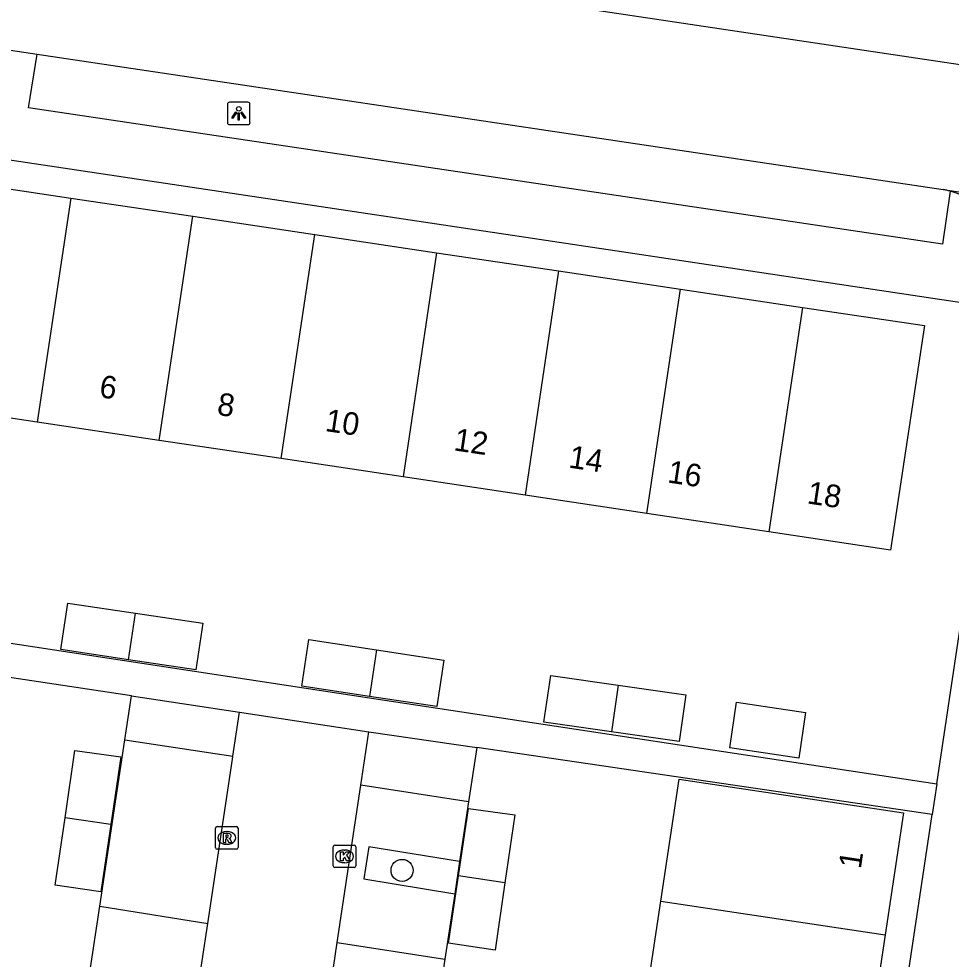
# Model space of a CAD drawing. Extents: x 164150 to 165261, y 382513 to 383432.
# Drawn here: x 164272.17 to 164313.46, y 382840.05 to 382881.72 of the extents above; entities that cross this region are included whole.
import ezdxf

# ---------------------------------------------------------------- set-up
doc = ezdxf.new("R2010")
doc.units = 0
for name, color, linetype in [('IMGEO_Boom', 7, 'Continuous'), ('IMGEO_Groenvoorziening', 7, 'Continuous'), ('IMGEO_Kolk', 7, 'Continuous'), ('IMGEO_Lichtpunt', 7, 'Continuous'), ('IMGEO_Pand', 7, 'Continuous'), ('IMGEO_Pand_nummerreeks', 7, 'Continuous'), ('IMGEO_Parkeervlak_open', 7, 'Continuous'), ('IMGEO_Rijbaan_lokaal_gesloten', 7, 'Continuous'), ('IMGEO_Rijbaan_lokaal_open', 7, 'Continuous'), ('IMGEO_Rioolput', 7, 'Continuous'), ('IMGEO_Voetpad_open', 7, 'Continuous')]:
    doc.layers.add(name, color=color, linetype=linetype)

msp = doc.modelspace()

# ---------------------------------------------------------------- linework, layer by layer
at = {"layer": 'IMGEO_Boom'}
msp.add_circle((164289.145, 382843.98), 0.489, dxfattribs=at)
at = {"layer": 'IMGEO_Groenvoorziening'}
msp.add_lwpolyline([(164291.688, 382844.368), (164291.474, 382842.945)], dxfattribs=at)
at = {"layer": 'IMGEO_Kolk'}
for p, q in [((164286.092, 382844.176), (164286.092, 382845.028)), ((164286.167, 382845.102), (164287.019, 382845.102)), ((164286.58, 382844.882), (164286.605, 382844.882)), ((164287.093, 382845.028), (164287.093, 382844.176)), ((164287.019, 382844.102), (164286.167, 382844.102)), ((164286.603, 382844.322), (164286.578, 382844.322))]:
    msp.add_line(p, q, dxfattribs=at)
for points in [[(164286.092, 382844.176), (164286.092, 382845.028)], [(164286.167, 382845.102), (164287.019, 382845.102)], [(164287.093, 382845.028), (164287.093, 382844.176)], [(164286.413, 382844.802), (164286.536, 382844.802), (164286.536, 382844.651), (164286.666, 382844.802), (164286.83, 382844.802), (164286.684, 382844.651), (164286.837, 382844.402), (164286.685, 382844.402), (164286.6, 382844.566), (164286.536, 382844.499), (164286.536, 382844.402), (164286.413, 382844.402), (164286.413, 382844.802)], [(164287.019, 382844.102), (164286.167, 382844.102)]]:
    msp.add_lwpolyline(points, dxfattribs=at)
for centre, start, end in [((164286.169, 382845.026), 91.552, 178.448), ((164286.169, 382845.026), 91.552, 178.448), ((164287.017, 382845.026), 1.552, 88.448), ((164287.017, 382845.026), 1.552, 88.448), ((164286.169, 382844.178), 181.552, 268.448), ((164286.169, 382844.178), 181.552, 268.448), ((164287.017, 382844.178), 271.552, 358.448), ((164287.017, 382844.178), 271.552, 358.448)]:
    msp.add_arc(centre, 0.0765, start, end, dxfattribs=at)
for centre, major_axis, ratio, start_param, end_param in [((164286.579, 382844.602), (-0.387, 0.002), 0.722429, 4.712389, 7.853982), ((164286.604, 382844.602), (-0.39, 0.002), 0.717154, 1.570796, 4.712389)]:
    msp.add_ellipse(centre, major_axis=major_axis, ratio=ratio, start_param=start_param, end_param=end_param, dxfattribs=at)
at = {"layer": 'IMGEO_Lichtpunt'}
for p, q in [((164281.411, 382877.927), (164281.411, 382877.12)), ((164281.411, 382877.927), (164281.411, 382877.12)), ((164282.313, 382878.022), (164281.505, 382878.022)), ((164282.313, 382878.022), (164281.505, 382878.022)), ((164282.407, 382877.12), (164282.407, 382877.927)), ((164282.407, 382877.12), (164282.407, 382877.927)), ((164281.505, 382877.026), (164282.313, 382877.026)), ((164281.505, 382877.026), (164282.313, 382877.026))]:
    msp.add_line(p, q, dxfattribs=at)
for points in [[(164281.785, 382877.591), (164281.824, 382877.563), (164281.636, 382877.301), (164281.598, 382877.328), (164281.785, 382877.591)], [(164281.887, 382877.543), (164281.934, 382877.543), (164281.934, 382877.221), (164281.887, 382877.221), (164281.887, 382877.543)], [(164281.997, 382877.563), (164282.035, 382877.59), (164282.222, 382877.328), (164282.183, 382877.3), (164281.997, 382877.563)]]:
    msp.add_lwpolyline(points, dxfattribs=at)
msp.add_circle((164281.91, 382877.725), 0.0994, dxfattribs=at)
for centre, start, end in [((164281.505, 382877.927), 90, 180), ((164281.505, 382877.927), 90, 180), ((164282.313, 382877.927), 0, 90), ((164282.313, 382877.927), 0, 90), ((164281.505, 382877.12), 180, 270), ((164281.505, 382877.12), 180, 270), ((164282.313, 382877.12), 270, 0), ((164282.313, 382877.12), 270, 360)]:
    msp.add_arc(centre, 0.0946, start, end, dxfattribs=at)
at = {"layer": 'IMGEO_Pand'}
for points in [[(164269.072, 382874.581), (164274.472, 382873.774)], [(164274.472, 382873.774), (164272.988, 382863.848)], [(164274.472, 382873.774), (164279.873, 382872.966)], [(164278.388, 382863.036), (164279.873, 382872.966)], [(164279.873, 382872.966), (164285.273, 382872.158)], [(164283.787, 382862.225), (164285.273, 382872.158)], [(164285.273, 382872.158), (164290.673, 382871.351)], [(164290.673, 382871.351), (164289.187, 382861.413)], [(164290.673, 382871.351), (164296.073, 382870.543)], [(164296.073, 382870.543), (164294.587, 382860.602)], [(164296.073, 382870.543), (164301.474, 382869.735)], [(164299.986, 382859.79), (164301.474, 382869.735)], [(164301.474, 382869.735), (164306.874, 382868.928)], [(164306.874, 382868.928), (164312.274, 382868.12), (164310.768, 382858.17), (164305.386, 382858.979)], [(164306.874, 382868.928), (164305.386, 382858.979)], [(164272.988, 382863.848), (164267.588, 382864.659)], [(164278.388, 382863.036), (164272.988, 382863.848)], [(164283.787, 382862.225), (164278.388, 382863.036)], [(164289.187, 382861.413), (164283.787, 382862.225)], [(164294.587, 382860.602), (164289.187, 382861.413)], [(164299.986, 382859.79), (164294.587, 382860.602)], [(164305.386, 382858.979), (164299.986, 382859.79)], [(164277.026, 382853.315), (164274.029, 382853.771), (164274.345, 382855.822), (164277.333, 382855.377)], [(164277.333, 382855.377), (164280.321, 382854.932), (164280.008, 382852.862), (164277.026, 382853.315)], [(164277.026, 382853.315), (164277.333, 382855.377)], [(164287.694, 382851.691), (164284.705, 382852.144), (164285.017, 382854.208), (164288.008, 382853.754)], [(164288.008, 382853.754), (164290.998, 382853.3), (164290.683, 382851.238), (164287.694, 382851.691)], [(164288.008, 382853.754), (164287.694, 382851.691)], [(164298.419, 382850.121), (164295.413, 382850.555), (164295.725, 382852.616), (164298.717, 382852.185)], [(164298.717, 382852.185), (164301.708, 382851.753), (164301.41, 382849.689), (164298.419, 382850.121)], [(164298.717, 382852.185), (164298.419, 382850.121)], [(164303.958, 382851.428), (164307.011, 382850.98), (164306.714, 382848.957), (164303.661, 382849.405), (164303.958, 382851.428)], [(164274.219, 382846.309), (164274.655, 382849.299), (164276.68, 382849.014), (164276.241, 382846.013)], [(164300.598, 382842.61), (164301.407, 382848.016), (164311.351, 382846.529), (164310.54, 382841.122)], [(164291.639, 382843.739), (164292.079, 382846.728), (164294.135, 382846.437), (164293.696, 382843.435)], [(164276.241, 382846.013), (164275.805, 382843.03), (164273.782, 382843.318), (164274.219, 382846.309)], [(164276.241, 382846.013), (164274.219, 382846.309)], [(164293.696, 382843.435), (164293.259, 382840.444), (164291.198, 382840.749), (164291.639, 382843.739)], [(164293.696, 382843.435), (164291.639, 382843.739)], [(164299.789, 382837.204), (164300.598, 382842.61)], [(164300.598, 382842.61), (164310.54, 382841.122)], [(164310.54, 382841.122), (164309.73, 382835.716)]]:
    msp.add_lwpolyline(points, dxfattribs=at)
at = {"layer": 'IMGEO_Parkeervlak_open'}
for points in [[(164275.756, 382842.39), (164276.86, 382849.764)], [(164292.087, 382847.018), (164291.688, 382844.368)], [(164291.688, 382844.368), (164287.669, 382845.027), (164287.445, 382843.608), (164291.474, 382842.945)], [(164291.474, 382842.945), (164291.038, 382840.051)]]:
    msp.add_lwpolyline(points, dxfattribs=at)
at = {"layer": 'IMGEO_Rijbaan_lokaal_gesloten'}
for points in [[(164314.585, 382879.574), (164314.161, 382879.638), (164274.826, 382885.521)], [(164271.199, 382880.418), (164272.98, 382880.152)], [(164272.98, 382880.152), (164313.111, 382874.159)]]:
    msp.add_lwpolyline(points, dxfattribs=at)
at = {"layer": 'IMGEO_Rijbaan_lokaal_open'}
for points in [[(164313.111, 382874.159), (164328.53, 382871.849)], [(164281.646, 382849.047), (164281.938, 382850.991)], [(164281.938, 382850.991), (164287.676, 382850.126)], [(164287.319, 382847.752), (164287.676, 382850.126)], [(164280.533, 382841.634), (164281.626, 382848.909), (164281.646, 382849.047)], [(164286.273, 382840.788), (164287.319, 382847.752)], [(164280.035, 382838.315), (164280.533, 382841.634)], [(164285.773, 382837.462), (164286.273, 382840.788)]]:
    msp.add_lwpolyline(points, dxfattribs=at)
for centre, radius, start, end in [((164311.799, 382868.73), 5.585, 73.2037, 76.4145), ((164311.657, 382868.188), 6.145, 28.4627, 73.3946)]:
    msp.add_arc(centre, radius, start, end, dxfattribs=at)
at = {"layer": 'IMGEO_Rioolput'}
for p, q in [((164280.878, 382844.992), (164280.878, 382845.844)), ((164280.953, 382845.918), (164281.805, 382845.918)), ((164281.366, 382845.698), (164281.391, 382845.698)), ((164281.879, 382845.844), (164281.879, 382844.992)), ((164281.805, 382844.918), (164280.953, 382844.918)), ((164281.389, 382845.138), (164281.364, 382845.138))]:
    msp.add_line(p, q, dxfattribs=at)
for points in [[(164280.878, 382844.992), (164280.878, 382845.844)], [(164280.953, 382845.918), (164281.805, 382845.918)], [(164281.879, 382845.844), (164281.879, 382844.992)], [(164281.467, 382845.616), (164281.215, 382845.618), (164281.215, 382845.218)], [(164281.215, 382845.218), (164281.339, 382845.218), (164281.339, 382845.38), (164281.35, 382845.38)], [(164281.393, 382845.537), (164281.339, 382845.537), (164281.339, 382845.456)], [(164281.339, 382845.456), (164281.391, 382845.456)], [(164281.397, 382845.351), (164281.468, 382845.218), (164281.608, 382845.218), (164281.543, 382845.344)], [(164281.805, 382844.918), (164280.953, 382844.918)]]:
    msp.add_lwpolyline(points, dxfattribs=at)
for centre, radius, start, end in [((164280.955, 382845.842), 0.0765, 91.552, 178.448), ((164280.955, 382845.842), 0.0765, 91.552, 178.448), ((164281.803, 382845.842), 0.0765, 1.552, 88.448), ((164281.803, 382845.842), 0.0765, 1.552, 88.448), ((164281.349, 382845.327), 0.0533, 26.0293, 88.6989), ((164281.375, 382845.645), 0.19, 274.7715, 282.9687), ((164281.399, 382845.441), 0.0964, 77.0061, 93.1865), ((164281.413, 382845.498), 0.0378, 276.6634, 79.6772), ((164281.466, 382845.506), 0.109, 350.3612, 89.416), ((164281.464, 382845.506), 0.112, 277.5842, 350.9817), ((164281.448, 382845.291), 0.108, 29.5134, 73.7905), ((164280.955, 382844.994), 0.0765, 181.552, 268.448), ((164280.955, 382844.994), 0.0765, 181.552, 268.448), ((164281.803, 382844.994), 0.0765, 271.552, 358.448), ((164281.803, 382844.994), 0.0765, 271.552, 358.448)]:
    msp.add_arc(centre, radius, start, end, dxfattribs=at)
for centre, major_axis, ratio, start_param, end_param in [((164281.365, 382845.418), (-0.387, 0.002), 0.722429, 4.712389, 7.853982), ((164281.39, 382845.418), (-0.39, 0.002), 0.717154, 1.570796, 4.712389)]:
    msp.add_ellipse(centre, major_axis=major_axis, ratio=ratio, start_param=start_param, end_param=end_param, dxfattribs=at)
at = {"layer": 'IMGEO_Voetpad_open'}
for points in [[(164313.413, 382874.077), (164313.081, 382871.736), (164272.599, 382877.773), (164272.98, 382880.152)], [(164260.822, 382877.103), (164315.414, 382868.927)], [(164312.82, 382847.812), (164315.881, 382868.253), (164315.414, 382868.927)], [(164257.168, 382856.277), (164287.898, 382851.603), (164312.82, 382847.812)], [(164277.152, 382851.711), (164256.94, 382854.753)], [(164276.86, 382849.764), (164277.152, 382851.711)], [(164277.152, 382851.711), (164281.938, 382850.991)], [(164287.676, 382850.126), (164292.449, 382849.423)], [(164276.86, 382849.764), (164281.646, 382849.047)], [(164292.449, 382849.423), (164292.087, 382847.018)], [(164312.617, 382846.453), (164292.449, 382849.423)], [(164292.087, 382847.018), (164287.319, 382847.752)], [(164312.82, 382847.812), (164312.617, 382846.453)], [(164306.097, 382802.914), (164312.617, 382846.453)], [(164275.258, 382839.069), (164275.756, 382842.39)], [(164275.756, 382842.39), (164280.533, 382841.634)], [(164286.273, 382840.788), (164291.038, 382840.051)], [(164291.038, 382840.051), (164290.538, 382836.727)]]:
    msp.add_lwpolyline(points, dxfattribs=at)

# ---------------------------------------------------------------- texts
at = {"layer": 'IMGEO_Pand_nummerreeks'}
for s, rotation, p in [('6', 351.4515, (164275.694, 382864.958)), ('8', 351.4515, (164280.912, 382864.174)), ('10', 351.4515, (164285.698, 382863.454)), ('12', 351.4515, (164291.396, 382862.598)), ('14', 351.4515, (164296.487, 382861.833)), ('16', 351.4515, (164300.862, 382861.175)), ('18', 351.4515, (164307.044, 382860.246)), ('1', 81.4746, (164309.458, 382844.02))]:
    msp.add_text(s, height=1, rotation=rotation, dxfattribs=at).set_placement(p)

doc.saveas('drawing.dxf')
